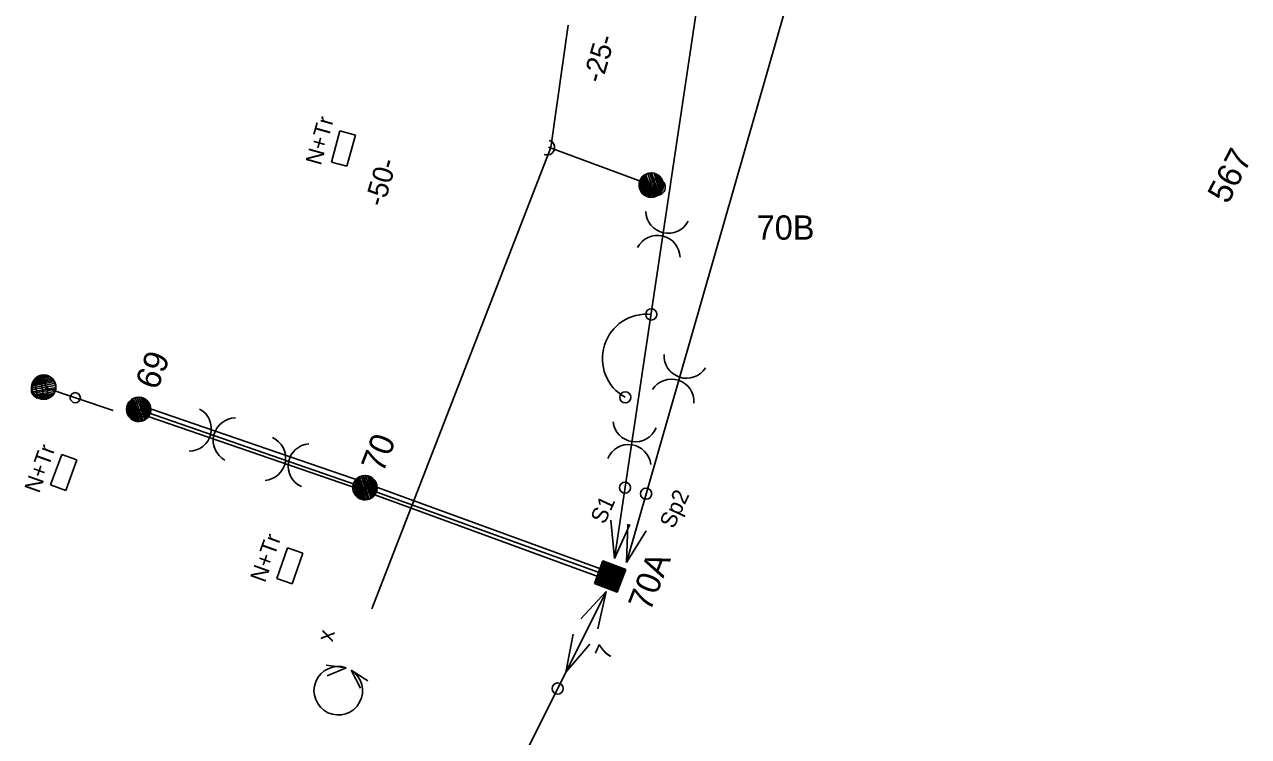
# Model space of a CAD drawing. Extents: x -595867 to -593796, y -1159595 to -1157495.
# Drawn here: x -594729.5 to -594654, y -1158027.2 to -1157983.3 of the extents above; entities that cross this region are included whole.
import ezdxf

# ---------------------------------------------------------------- set-up
doc = ezdxf.new("R2010")
doc.units = 0
for name, color, linetype in [('BVK_kanalizace_destova_nova', 7, 'Continuous'), ('BVK_kanalizace_jednotna_nova', 7, 'Continuous'), ('CD Telematika_novy', 7, 'Continuous')]:
    doc.layers.add(name, color=color, linetype=linetype)

# ---------------------------------------------------------------- blocks, each defined once
blk = doc.blocks.new('st_1t')
for points in [[(-0.00742, 0.00071), (0.00284, 0.0069), (0.00359, 0.00656), (-0.00747, -0.00023)], [(-0.00747, -0.00023), (0.00359, 0.00656), (0.00442, 0.00605), (-0.00743, -0.00101)], [(-0.00743, -0.00101), (0.00442, 0.00605), (0.00522, 0.0054), (-0.00722, -0.0019)], [(-0.00729, 0.00159), (0.00185, 0.00722), (0.00284, 0.0069), (-0.00742, 0.00071)], [(-0.00711, 0.00221), (0.00057, 0.00744), (0.00185, 0.00722), (-0.00729, 0.00159)], [(-0.00722, -0.0019), (0.00522, 0.0054), (0.00588, 0.00461), (-0.00688, -0.00302)], [(-0.00689, 0.00294), (-0.00011, 0.00749), (0.00057, 0.00744), (-0.00711, 0.00221)], [(-0.00669, 0.00331), (-0.00149, 0.00733), (-0.00011, 0.00749), (-0.00689, 0.00294)], [(-0.00688, -0.00302), (0.00588, 0.00461), (0.00666, 0.00341), (-0.00639, -0.00386)], [(-0.00627, 0.00403), (-0.00222, 0.00714), (-0.00149, 0.00733), (-0.00669, 0.00331)], [(-0.00639, -0.00386), (0.00666, 0.00341), (0.00712, 0.00224), (-0.00567, -0.00488)], [(-0.00579, 0.00472), (-0.00315, 0.00675), (-0.00222, 0.00714), (-0.00627, 0.00403)], [(-0.00526, 0.00533), (-0.00413, 0.00624), (-0.00315, 0.00675), (-0.00579, 0.00472)], [(-0.00567, -0.00488), (0.00712, 0.00224), (0.00742, 0.00112), (-0.00488, -0.00564)], [(-0.00488, -0.00564), (0.00742, 0.00112), (0.00748, -0.00042), (-0.00405, -0.00629)], [(-0.00405, -0.00629), (0.00748, -0.00042), (0.00729, -0.00175), (-0.00317, -0.00679)], [(-0.00317, -0.00679), (0.00729, -0.00175), (0.00698, -0.00275), (-0.00206, -0.00718)], [(-0.00206, -0.00718), (0.00698, -0.00275), (0.00651, -0.0037), (-0.00114, -0.0074)], [(-0.00114, -0.0074), (0.00651, -0.0037), (0.00592, -0.00458), (-0.00048, -0.00747)], [(-0.00048, -0.00747), (0.00592, -0.00458), (0.00536, -0.00524), (0.00037, -0.00747)], [(0.00037, -0.00747), (0.00536, -0.00524), (0.00449, -0.00597), (0.00138, -0.00739)], [(0.00138, -0.00739), (0.00449, -0.00597), (0.00384, -0.00644), (0.0025, -0.00702)], [(0.0025, -0.00702), (0.00384, -0.00644), (0.00295, -0.00692), (0.00293, -0.00693)]]:
    blk.add_lwpolyline(points, close=True)
blk.add_circle((0, 0), 0.0075)
blk = doc.blocks.new('st_bp')
for p, q in [((0.0075, 0.0075), (-0.0075, 0.0075)), ((-0.0075, 0.0075), (-0.0075, -0.0075)), ((-0.0075, -0.0075), (0.0075, 0.0075)), ((-0.0075, -0.00708), (0.00708, 0.0075)), ((-0.0075, -0.00665), (0.00665, 0.0075)), ((-0.0075, -0.00623), (0.00623, 0.0075)), ((-0.0075, -0.0058), (0.0058, 0.0075)), ((-0.0075, -0.00538), (0.00538, 0.0075)), ((-0.0075, -0.00495), (0.00495, 0.0075)), ((-0.0075, -0.00453), (0.00453, 0.0075)), ((-0.0075, -0.00411), (0.00411, 0.0075)), ((-0.0075, -0.00368), (0.00368, 0.0075)), ((-0.0075, -0.00326), (0.00326, 0.0075)), ((-0.0075, -0.00283), (0.00283, 0.0075)), ((-0.0075, -0.00241), (0.00241, 0.0075)), ((-0.0075, -0.00198), (0.00198, 0.0075)), ((-0.0075, -0.00156), (0.00156, 0.0075)), ((-0.0075, -0.00114), (0.00114, 0.0075)), ((-0.0075, -0.00071), (0.00071, 0.0075)), ((-0.0075, -0.00029), (0.00029, 0.0075)), ((-0.0075, 0.00014), (-0.00014, 0.0075)), ((-0.0075, 0.00056), (-0.00056, 0.0075)), ((-0.0075, 0.00099), (-0.00099, 0.0075)), ((-0.0075, 0.00141), (-0.00141, 0.0075)), ((-0.0075, 0.00183), (-0.00183, 0.0075)), ((-0.0075, 0.00226), (-0.00226, 0.0075)), ((-0.0075, 0.00268), (-0.00268, 0.0075)), ((-0.0075, 0.00311), (-0.00311, 0.0075)), ((-0.0075, 0.00353), (-0.00353, 0.0075)), ((-0.0075, 0.00396), (-0.00396, 0.0075)), ((-0.0075, 0.00438), (-0.00438, 0.0075)), ((-0.0075, 0.0048), (-0.0048, 0.0075)), ((-0.0075, 0.00523), (-0.00523, 0.0075)), ((-0.0075, 0.00565), (-0.00565, 0.0075)), ((-0.0075, 0.00608), (-0.00608, 0.0075)), ((-0.0075, 0.0065), (-0.0065, 0.0075)), ((-0.0075, 0.00692), (-0.00692, 0.0075)), ((-0.0075, 0.00735), (-0.00735, 0.0075)), ((-0.00708, -0.0075), (0.0075, 0.00708)), ((-0.00665, -0.0075), (0.0075, 0.00665)), ((-0.00623, -0.0075), (0.0075, 0.00623)), ((-0.0058, -0.0075), (0.0075, 0.0058)), ((-0.00538, -0.0075), (0.0075, 0.00538)), ((-0.00495, -0.0075), (0.0075, 0.00495)), ((-0.00453, -0.0075), (0.0075, 0.00453)), ((-0.00411, -0.0075), (0.0075, 0.00411)), ((-0.00368, -0.0075), (0.0075, 0.00368)), ((-0.00326, -0.0075), (0.0075, 0.00326)), ((-0.00283, -0.0075), (0.0075, 0.00283)), ((-0.00241, -0.0075), (0.0075, 0.00241)), ((-0.00198, -0.0075), (0.0075, 0.00198)), ((-0.00156, -0.0075), (0.0075, 0.00156)), ((-0.00114, -0.0075), (0.0075, 0.00114)), ((-0.00071, -0.0075), (0.0075, 0.00071)), ((-0.00029, -0.0075), (0.0075, 0.00029)), ((0.0075, -0.0075), (0.0075, 0.0075)), ((-0.0075, -0.0075), (0.0075, -0.0075)), ((0.00014, -0.0075), (0.0075, -0.00014)), ((0.00056, -0.0075), (0.0075, -0.00056)), ((0.00099, -0.0075), (0.0075, -0.00099)), ((0.00141, -0.0075), (0.0075, -0.00141)), ((0.00183, -0.0075), (0.0075, -0.00183)), ((0.00226, -0.0075), (0.0075, -0.00226)), ((0.00268, -0.0075), (0.0075, -0.00268)), ((0.00311, -0.0075), (0.0075, -0.00311)), ((0.00353, -0.0075), (0.0075, -0.00353)), ((0.00396, -0.0075), (0.0075, -0.00396)), ((0.00438, -0.0075), (0.0075, -0.00438)), ((0.0048, -0.0075), (0.0075, -0.0048)), ((0.00523, -0.0075), (0.0075, -0.00523)), ((0.00565, -0.0075), (0.0075, -0.00565)), ((0.00608, -0.0075), (0.0075, -0.00608)), ((0.0065, -0.0075), (0.0075, -0.0065)), ((0.00692, -0.0075), (0.0075, -0.00692)), ((0.00735, -0.0075), (0.0075, -0.00735))]:
    blk.add_line(p, q)
blk = doc.blocks.new('st_tecka')
blk.add_circle((0, 0), 0.00314)
blk = doc.blocks.new('st1k_1t')
blk.add_line((0, 0), (0.04531, 0))
blk.add_blockref('st_1t', (0, 0))
at = {"rotation": 90}
blk.add_blockref('st_tecka', (0.02054, 0), dxfattribs=at)
blk = doc.blocks.new('kotv_tecka')
blk.add_circle((0, 0), 0.00345)
blk = doc.blocks.new('kotv_polok')
for p, q in [((-0.05578, 0), (-0.03278, 0.00647)), ((-0.05578, 0), (-0.03363, -0.00562)), ((0, 0), (-0.02299, -0.00565))]:
    blk.add_line(p, q)
blk.add_lwpolyline([(0, 0), (-0.02214, 0.00639)])
blk.add_blockref('kotv_tecka', (-0.06698, 0))
blk = doc.blocks.new('kotv_pev')
blk.add_line((0, 0), (-0.02299, -0.00565))
blk.add_lwpolyline([(0, 0), (-0.02214, 0.00639)])
blk.add_blockref('kotv_tecka', (-0.04416, 0))
blk = doc.blocks.new('pol_izol')
for centre, start, end in [((-0.01484, 0), 284.40471, 75.59529), ((0.01484, 0), 104.40471, 255.59529)]:
    blk.add_arc(centre, 0.01384, start, end)
blk = doc.blocks.new('pol_proplan')
blk.add_arc((0.02681, -0.00542), 0.02735, 11.43413, 168.56587)
for p in [(0, 0), (0.05362, 0)]:
    blk.add_blockref('kotv_tecka', p)
blk = doc.blocks.new('pol_sipka2')
for q in [(0.01228, 0.00302), (0.01182, -0.00341)]:
    blk.add_line((0, 0), q)
blk = doc.blocks.new('pol_sjsp')
for p, q in [((-0.01, 0.005), (0.01, 0.005)), ((-0.01, -0.005), (-0.01, 0.005)), ((0.01, 0.005), (0.01, -0.005)), ((0.01, -0.005), (-0.01, -0.005))]:
    blk.add_line(p, q)

msp = doc.modelspace()

# ---------------------------------------------------------------- linework, layer by layer
at = {"layer": 'BVK_kanalizace_destova_nova'}
for p, q in [((-594686.064, -1157969.17), (-594693.126, -1158016.239)), ((-594679.508, -1157971.641), (-594692.383, -1158016.491)), ((-594690.849, -1157993.191), (-594697.189, -1157990.857)), ((-594722.489, -1158007.04), (-594708.523, -1158011.876)), ((-594708.523, -1158011.876), (-594693.39, -1158017.36)), ((-594716.344, -1158063.661), (-594693.627, -1158018.287))]:
    msp.add_line(p, q, dxfattribs=at)
at = {"layer": 'BVK_kanalizace_jednotna_nova'}
for p, q in [((-594690.592, -1157993.802), (-594690.752, -1157992.903)), ((-594690.222, -1157993.744), (-594690.384, -1157992.832)), ((-594728.722, -1158006.342), (-594728.882, -1158005.443)), ((-594728.352, -1158006.284), (-594728.514, -1158005.372)), ((-594722.543, -1158007.523), (-594722.703, -1158006.624)), ((-594722.173, -1158007.465), (-594722.335, -1158006.553)), ((-594708.782, -1158012.263), (-594708.942, -1158011.364)), ((-594708.412, -1158012.205), (-594708.574, -1158011.293)), ((-594693.206, -1158016.894), (-594693.833, -1158017.126)), ((-594692.728, -1158017.117), (-594694.051, -1158017.606)), ((-594692.95, -1158017.598), (-594693.569, -1158017.827))]:
    msp.add_line(p, q, dxfattribs=at)
for points in [[(-594708.591, -1158011.542), (-594722.348, -1158006.803)], [(-594708.754, -1158012.015), (-594722.511, -1158007.276)], [(-594693.301, -1158017.126), (-594708.584, -1158011.545)], [(-594693.472, -1158017.595), (-594708.755, -1158012.014)], [(-594693.144, -1158018.022), (-594694.053, -1158017.604), (-594693.636, -1158016.696), (-594692.727, -1158017.114), (-594693.144, -1158018.022)]]:
    msp.add_lwpolyline(points, dxfattribs=at)
msp.add_lwpolyline([(-594693.144, -1158018.022), (-594694.053, -1158017.604), (-594693.636, -1158016.696), (-594692.727, -1158017.114)], close=True, dxfattribs=at)
for centre in [(-594690.479, -1157993.319), (-594690.479, -1157993.319), (-594728.609, -1158005.859), (-594728.609, -1158005.859), (-594722.43, -1158007.04), (-594722.43, -1158007.04), (-594708.669, -1158011.78), (-594708.669, -1158011.78)]:
    msp.add_circle(centre, 0.5, dxfattribs=at)
at = {"layer": 'CD Telematika_novy'}
for p, q in [((-594697.046, -1157990.867), (-594695.971, -1157983.319)), ((-594708.1, -1158019.351), (-594697.046, -1157990.867))]:
    msp.add_line(p, q, dxfattribs=at)
for centre, radius, start, end in [((-594697.275, -1157990.874), 0.46, 246.52925, 72.95166), ((-594710.168, -1158024.411), 1.5, 71.40518, 58.2546)]:
    msp.add_arc(centre, radius, start, end, dxfattribs=at)

# ---------------------------------------------------------------- block references
at = {"layer": 'BVK_kanalizace_destova_nova'}
for name, p, xscale, yscale, rotation in [('st_1t', (-594690.849, -1157993.191), 100.00000000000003, 99.99999999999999, 79.51685128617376), ('pol_izol', (-594690.13, -1157996.231), 100, 100, 77.28980931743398), ('pol_proplan', (-594692.453, -1158006.293), 100.00000000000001, 100, 72.56646319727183), ('pol_izol', (-594689.132, -1158005.143), 99.99999999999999, 100.00000000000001, 71.74682109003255), ('st1k_1t', (-594728.35, -1158005.665), 99.99999999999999, 100, -18.575780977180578), ('st_1t', (-594722.489, -1158007.04), 100.00000000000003, 99.99999999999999, 79.51685128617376), ('pol_izol', (-594717.947, -1158008.594), 100.00000000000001, 99.99999999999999, -13.963792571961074), ('pol_izol', (-594692.041, -1158009.126), 100, 100, 81.86058869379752), ('pol_izol', (-594713.338, -1158010.292), 100, 100.00000000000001, -9.647031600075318), ('st_1t', (-594708.523, -1158011.876), 100.00000000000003, 99.99999999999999, 79.51685128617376), ('kotv_pev', (-594693.126, -1158016.239), 100, 100.00000000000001, -98.53322212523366), ('kotv_pev', (-594692.383, -1158016.491), 100.00000000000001, 100, -106.0173462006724), ('st_bp', (-594693.39, -1158017.36), 100.00000000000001, 99.99999999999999, 159.34889956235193), ('kotv_polok', (-594693.627, -1158018.287), 100.00000000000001, 99.99999999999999, 63.40541094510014)]:
    msp.add_blockref(name, p, dxfattribs=dict(at, xscale=xscale, yscale=yscale, rotation=rotation))
at = {"layer": 'CD Telematika_novy'}
for name, p, xscale, yscale, rotation in [('pol_sjsp', (-594709.852, -1157990.934), 100.00000000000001, 100, 74.86686238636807), ('pol_sjsp', (-594727.113, -1158010.928), 99.99999999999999, 100.00000000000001, 70.09293090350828), ('pol_sjsp', (-594713.159, -1158016.704), 100, 100, 70.69734381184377), ('pol_sipka2', (-594709.69, -1158022.989), 100, 100, -170.87057120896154), ('pol_sipka2', (-594709.379, -1158023.135), 100, -100, -48.748359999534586)]:
    msp.add_blockref(name, p, dxfattribs=dict(at, xscale=xscale, yscale=yscale, rotation=rotation))

# ---------------------------------------------------------------- texts
at = {"layer": 'BVK_kanalizace_destova_nova'}
for s, height, rotation, p in [('-25-', 1.25, 73.76306, (-594693.893, -1157986.954)), ('-50-', 1.25, 73.76306, (-594707.366, -1157994.594)), ('69', 1.5, 68.56762, (-594721.349, -1158005.908)), ('70', 1.5, 68.56762, (-594707.409, -1158011.014)), ('Sp2', 1, 65.20671, (-594689.469, -1158014.461)), ('S1', 1, 65.20671, (-594693.733, -1158014.18)), ('70A', 1.5, 68.56762, (-594690.923, -1158019.576)), ('7', 1, 65.20671, (-594693.471, -1158022.556))]:
    msp.add_text(s, height=height, rotation=rotation, dxfattribs=at).set_placement(p)
at = {"layer": 'BVK_kanalizace_jednotna_nova'}
msp.add_text('567', height=1.5, rotation=62.62089, dxfattribs=at).set_placement((-594655.253, -1157994.426))
msp.add_text('70B', height=1.5, dxfattribs=at).set_placement((-594684.34, -1157996.56))
at = {"layer": 'CD Telematika_novy'}
for s, rotation, p in [('N+Tr', 74.34606, (-594711.245, -1157992.02)), ('N+Tr', 70.27841, (-594728.635, -1158012.266)), ('N+Tr', 70.27841, (-594714.697, -1158017.783)), ('x', 77.795, (-594710.514, -1158021.426))]:
    msp.add_text(s, height=1, rotation=rotation, dxfattribs=at).set_placement(p)

doc.saveas('drawing.dxf')
